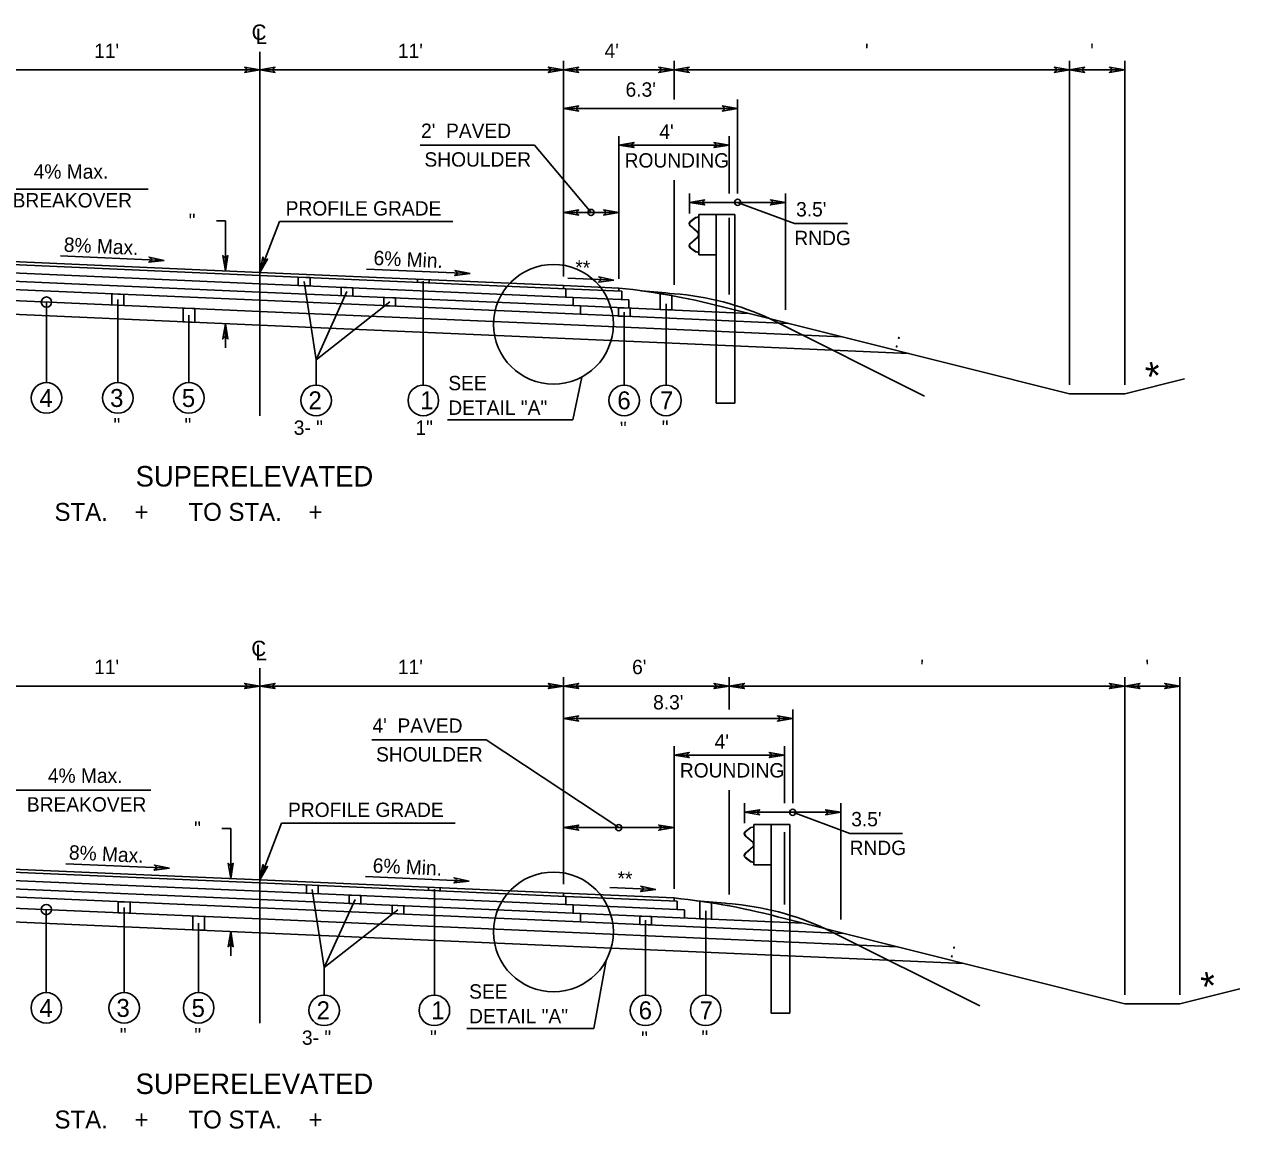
# Model space of a CAD drawing. Extents: x -592 to 1199, y -590 to 416.
# Drawn here: x 789.6 to 908.1, y -214.2 to -106.5 of the extents above; entities that cross this region are included whole.
import ezdxf

# ---------------------------------------------------------------- set-up
doc = ezdxf.new("R2010")
doc.units = 0
doc.layers.add('1', color=7, linetype='Continuous')
doc.layers.add('Des_ Drain_ Ftrs', color=7, linetype='Continuous')

msp = doc.modelspace()

# ---------------------------------------------------------------- linework, layer by layer
at = {"layer": '1'}
for p, q in [((812.53, -144.63), (812.53, -109.14)), ((842.16, -131.07), (842.16, -110.02)), ((852.94, -113.79), (852.94, -110.02)), ((891.52, -141.61), (891.52, -110.02)), ((896.91, -141.61), (896.91, -110.02)), ((812.53, -110.9), (782.89, -110.9)), ((812.53, -110.9), (842.16, -110.9)), ((842.16, -110.9), (852.94, -110.9)), ((852.94, -110.9), (891.52, -110.9)), ((891.52, -110.9), (896.91, -110.9)), ((859.14, -122.95), (859.14, -113.79)), ((842.16, -114.67), (859.14, -114.67)), ((847.55, -131.3), (847.55, -117.36)), ((858.33, -122.95), (858.33, -117.36)), ((839.32, -118.24), (828.18, -118.24)), ((844.85, -124.81), (839.32, -118.24)), ((847.55, -118.24), (858.33, -118.24)), ((852.94, -131.86), (852.94, -121.65)), ((801.62, -122.55), (787.67, -122.55)), ((854.44, -124.9), (854.44, -122.95)), ((863.83, -134.3), (863.83, -122.95)), ((854.44, -123.83), (863.83, -123.83)), ((859.14, -123.83), (864.69, -125.9)), ((809.17, -125.62), (808.29, -125.62)), ((809.17, -125.62), (809.17, -130.5)), ((842.16, -124.81), (847.55, -124.81)), ((855.04, -125.3), (854.52, -125.68)), ((855.05, -125.32), (854.54, -125.71)), ((855.36, -125.24), (855.04, -125.3)), ((855.36, -125.27), (855.05, -125.32)), ((855.36, -125.01), (855.36, -128.94)), ((855.36, -125.01), (857.04, -125.01)), ((857.04, -125.01), (857.04, -143.41)), ((858.87, -125.01), (857.04, -125.01)), ((858.33, -132.82), (858.33, -125.32)), ((858.87, -125.01), (858.87, -143.41)), ((812.53, -130.65), (814.44, -125.7)), ((831.35, -125.7), (814.44, -125.7)), ((854.51, -126.12), (855.24, -126.75)), ((854.53, -126.09), (855.26, -126.73)), ((864.69, -125.9), (869.85, -125.9)), ((855.24, -127.2), (854.51, -127.84)), ((855.26, -127.23), (854.53, -127.86)), ((855.33, -126.94), (855.33, -127.01)), ((855.36, -126.94), (855.36, -127.01)), ((793.09, -129.05), (803.21, -129.49)), ((854.52, -128.27), (855.04, -128.66)), ((854.54, -128.25), (855.05, -128.63)), ((855.04, -128.66), (855.36, -128.72)), ((855.05, -128.63), (855.36, -128.69)), ((855.36, -128.94), (857.04, -128.94)), ((812.53, -131.76), (781.62, -130.41)), ((812.53, -130.95), (782.54, -129.64)), ((812.53, -130.65), (782.88, -129.36)), ((822.93, -130.33), (833.04, -130.77)), ((812.53, -132.57), (780.7, -131.18)), ((842.17, -131.95), (812.53, -130.65)), ((842.4, -132.26), (812.53, -130.95)), ((816.86, -131.54), (818.02, -139.17)), ((828.48, -131.51), (828.48, -141.65)), ((847.07, -131.41), (842.58, -131.22)), ((812.53, -133.38), (780.7, -131.99)), ((843.1, -133.09), (812.53, -131.76)), ((843.81, -133.93), (812.53, -132.57)), ((821.03, -132.53), (818.02, -139.17)), ((847.55, -132.18), (842.17, -131.95)), ((842.17, -131.95), (842.17, -132.25)), ((847.84, -132.49), (842.4, -132.26)), ((842.4, -132.26), (842.4, -133.06)), ((847.55, -132.18), (847.55, -132.48)), ((847.84, -132.49), (847.84, -133.3)), ((812.53, -135.8), (758.02, -133.42)), ((812.53, -134.46), (780.7, -133.07)), ((791.71, -133.55), (791.71, -141.42)), ((798.68, -133.31), (798.68, -141.42)), ((843.81, -134.74), (812.53, -133.38)), ((825.21, -133.54), (818.02, -139.17)), ((848.54, -133.33), (843.1, -133.09)), ((843.1, -133.09), (843.1, -133.9)), ((843.81, -133.93), (843.81, -134.74)), ((860.16, -134.65), (843.81, -133.93)), ((848.54, -133.33), (848.54, -134.14)), ((852.16, -133.72), (852.16, -141.65)), ((854.44, -132.96), (854.44, -132.96)), ((805.61, -134.82), (805.61, -141.42)), ((842.17, -135.75), (812.53, -134.46)), ((864.08, -135.63), (843.81, -134.74)), ((848.08, -134.54), (848.08, -141.65)), ((858.33, -134.19), (891.52, -142.49)), ((809.17, -135.66), (809.17, -138.02)), ((875.84, -138.57), (812.53, -135.8)), ((869.31, -136.94), (842.17, -135.75)), ((862.33, -135.19), (877.38, -142.72)), ((818.02, -139.17), (818.02, -141.65)), ((843.96, -140.86), (843.07, -145.05)), ((902.74, -141.03), (896.91, -142.49)), ((858.87, -143.41), (857.04, -143.41)), ((891.52, -142.49), (896.91, -142.49)), ((830.84, -145.05), (843.07, -145.05)), ((812.53, -203.88), (812.53, -169.24)), ((842.16, -190.32), (842.16, -170.12)), ((858.33, -173.28), (858.33, -170.12)), ((896.91, -201.1), (896.91, -170.12)), ((902.3, -201.1), (902.3, -170.12)), ((812.53, -171), (782.89, -171)), ((812.53, -171), (842.16, -171)), ((842.16, -171), (858.33, -171)), ((858.33, -171), (896.91, -171)), ((896.91, -171), (902.3, -171)), ((842.16, -174.16), (864.52, -174.16)), ((864.52, -182.43), (864.52, -173.28)), ((834.6, -176.26), (823.46, -176.26)), ((847.55, -184.81), (834.6, -176.26)), ((852.94, -190.79), (852.94, -176.85)), ((852.94, -177.73), (863.71, -177.73)), ((863.71, -182.43), (863.71, -176.85)), ((801.91, -181.14), (788.43, -181.14)), ((858.33, -191.34), (858.33, -181.15)), ((859.83, -184.38), (859.83, -182.43)), ((869.21, -193.78), (869.21, -182.43)), ((859.83, -183.31), (869.21, -183.31)), ((864.52, -183.31), (870.08, -185.38)), ((809.69, -184.9), (808.81, -184.9)), ((809.69, -184.9), (809.69, -189.78)), ((812.53, -189.9), (814.66, -184.36)), ((831.58, -184.36), (814.66, -184.36)), ((842.16, -184.81), (852.94, -184.81)), ((860.42, -184.78), (859.91, -185.17)), ((860.44, -184.81), (859.93, -185.19)), ((860.74, -184.73), (860.42, -184.78)), ((860.74, -184.76), (860.44, -184.81)), ((860.74, -184.5), (860.74, -188.43)), ((860.74, -184.5), (862.42, -184.5)), ((862.42, -184.5), (862.42, -202.89)), ((864.25, -184.5), (862.42, -184.5)), ((864.25, -184.5), (864.25, -202.89)), ((859.89, -185.6), (860.62, -186.24)), ((859.91, -185.58), (860.64, -186.22)), ((863.71, -192.31), (863.71, -185.24)), ((870.08, -185.38), (875.23, -185.38)), ((860.62, -186.69), (859.89, -187.32)), ((860.64, -186.71), (859.91, -187.35)), ((860.71, -186.43), (860.71, -186.5)), ((860.74, -186.43), (860.74, -186.5)), ((793.6, -188.33), (803.71, -188.77)), ((859.91, -187.76), (860.42, -188.15)), ((859.93, -187.73), (860.44, -188.12)), ((860.42, -188.15), (860.74, -188.2)), ((860.44, -188.12), (860.74, -188.17)), ((860.74, -188.43), (862.42, -188.43)), ((812.53, -191.01), (781.62, -189.66)), ((812.53, -190.2), (782.54, -188.89)), ((812.53, -189.9), (782.88, -188.61)), ((822.85, -189.58), (832.96, -190.02)), ((812.53, -191.82), (780.7, -190.43)), ((842.17, -191.2), (812.53, -189.9)), ((842.4, -191.51), (812.53, -190.2)), ((817.65, -190.83), (818.81, -198.46)), ((829.56, -190.81), (829.56, -201.14)), ((851.17, -190.85), (846.67, -190.65)), ((812.53, -192.63), (780.72, -191.24)), ((843.1, -192.35), (812.53, -191.01)), ((843.81, -193.19), (812.53, -191.82)), ((821.83, -191.82), (818.81, -198.46)), ((852.94, -191.67), (842.17, -191.2)), ((842.17, -191.2), (842.17, -191.5)), ((853.26, -191.98), (842.4, -191.51)), ((842.4, -191.51), (842.4, -192.32)), ((852.94, -191.67), (852.94, -191.97)), ((853.26, -191.98), (853.26, -192.79)), ((812.53, -195.06), (753.04, -192.46)), ((812.53, -193.71), (780.7, -192.32)), ((791.7, -192.8), (791.7, -200.91)), ((799.29, -192.59), (799.29, -200.91)), ((843.81, -194), (812.53, -192.63)), ((826, -192.83), (818.81, -198.46)), ((853.96, -192.82), (843.1, -192.35)), ((843.1, -192.35), (843.1, -193.16)), ((843.81, -193.19), (843.81, -194)), ((865.55, -194.14), (843.81, -193.19)), ((853.96, -192.82), (853.96, -193.63)), ((856.03, -192.92), (856.03, -201.14)), ((859.83, -192.44), (859.83, -192.44)), ((806.56, -194.12), (806.56, -200.91)), ((843.77, -195.07), (812.53, -193.71)), ((869.47, -195.12), (843.81, -194)), ((850.16, -193.85), (850.16, -201.14)), ((863.71, -193.68), (896.91, -201.98)), ((809.69, -194.93), (809.69, -197.3)), ((881.23, -198.06), (812.53, -195.06)), ((874.7, -196.42), (843.77, -195.07)), ((867.71, -194.68), (882.76, -202.2)), ((846.31, -197.76), (845.13, -204.41)), ((818.81, -198.46), (818.81, -201.14)), ((908.13, -200.52), (902.3, -201.98)), ((896.91, -201.98), (902.3, -201.98)), ((864.25, -202.89), (862.42, -202.89)), ((832.73, -204.41), (845.13, -204.41))]:
    msp.add_line(p, q, dxfattribs=at)
for points in [[(816.28, -131.11), (817.43, -131.16), (817.43, -131.97), (816.28, -131.92)], [(827.91, -131.32), (829.05, -131.37), (829.05, -131.67), (827.91, -131.62)], [(798.1, -132.75), (799.25, -132.8), (799.25, -133.88), (798.1, -133.83)], [(820.46, -132.11), (821.6, -132.16), (821.6, -132.97), (820.46, -132.92)], [(851.59, -132.72), (852.73, -132.92), (852.73, -134.32), (851.59, -134.27)], [(824.63, -133.1), (825.78, -133.15), (825.78, -133.96), (824.63, -133.91)], [(805.04, -134.13), (806.18, -134.18), (806.18, -135.53), (805.04, -135.48)], [(847.51, -134.1), (848.65, -134.15), (848.65, -134.96), (847.51, -134.91)], [(817.08, -190.4), (818.22, -190.45), (818.22, -191.26), (817.08, -191.21)], [(828.99, -190.62), (830.13, -190.67), (830.13, -190.97), (828.99, -190.92)], [(798.72, -192.03), (799.87, -192.08), (799.87, -193.16), (798.72, -193.11)], [(821.25, -191.39), (822.4, -191.44), (822.4, -192.25), (821.25, -192.2)], [(855.46, -191.98), (856.61, -192.15), (856.61, -193.75), (855.46, -193.7)], [(825.43, -192.38), (826.58, -192.43), (826.58, -193.24), (825.43, -193.19)], [(805.99, -193.42), (807.13, -193.47), (807.13, -194.82), (805.99, -194.77)], [(849.59, -193.44), (850.73, -193.49), (850.73, -194.3), (849.59, -194.25)]]:
    msp.add_lwpolyline(points, close=True, dxfattribs=at)
for centre, radius in [((859.14, -123.83), 0.3), ((844.85, -124.81), 0.3), ((841.18, -135.72), 5.84), ((791.71, -133.55), 0.5), ((791.71, -142.9), 1.49), ((798.68, -142.9), 1.49), ((805.61, -142.9), 1.49), ((818.02, -143.14), 1.49), ((828.48, -143.14), 1.49), ((848.08, -143.14), 1.49), ((852.16, -143.14), 1.49), ((864.52, -183.31), 0.3), ((847.55, -184.81), 0.3), ((841.18, -194.98), 5.84), ((791.7, -192.8), 0.5), ((791.7, -202.39), 1.49), ((799.29, -202.39), 1.49), ((806.56, -202.39), 1.49), ((818.81, -202.63), 1.49), ((829.56, -202.63), 1.49), ((850.16, -202.63), 1.49), ((856.03, -202.63), 1.49)]:
    msp.add_circle(centre, radius, dxfattribs=at)
for centre, radius, start, end in [((854.69, -125.91), 0.278, 126.9799, 229.021), ((854.69, -125.91), 0.249, 126.9799, 229.021), ((855.08, -126.94), 0.249, 0, 49.0365), ((855.08, -126.94), 0.278, 0, 49.0365), ((854.69, -128.05), 0.278, 130.979, 233.0201), ((854.69, -128.05), 0.249, 130.979, 233.0201), ((855.08, -127.02), 0.249, 310.9635, 0), ((855.08, -127.02), 0.278, 310.9635, 0), ((840.66, -199.02), 67.19, 74.7593, 84.1179), ((842.12, -233.4), 101.24, 83.8633, 85.6775), ((850.82, -160.02), 27.37, 65.1374, 85.5513), ((860.07, -185.39), 0.278, 126.9799, 229.021), ((860.07, -185.39), 0.249, 126.9799, 229.021), ((860.07, -187.53), 0.278, 130.979, 233.0201), ((860.07, -187.53), 0.249, 130.979, 233.0201), ((860.46, -186.43), 0.249, 0, 49.0365), ((860.46, -186.5), 0.249, 310.9635, 0), ((860.46, -186.43), 0.278, 0, 49.0365), ((860.46, -186.5), 0.278, 310.9635, 0), ((846.05, -258.5), 67.19, 74.7602, 84.1188), ((847.5, -292.89), 101.24, 83.8633, 85.6775), ((856.2, -219.51), 27.37, 65.1374, 85.5513)]:
    msp.add_arc(centre, radius, start, end, dxfattribs=at)
at = {"layer": 'Des_ Drain_ Ftrs'}
for points in [[(812.53, -110.9), (811.04, -111.15), (811.33, -110.9), (811.04, -110.65)], [(812.53, -110.9), (814.01, -111.15), (813.72, -110.9), (814.01, -110.65)], [(842.16, -110.9), (840.67, -111.15), (840.97, -110.9), (840.67, -110.65)], [(842.16, -110.9), (843.65, -111.15), (843.35, -110.9), (843.65, -110.65)], [(852.94, -110.9), (851.45, -111.15), (851.74, -110.9), (851.45, -110.65)], [(852.94, -110.9), (854.43, -111.15), (854.13, -110.9), (854.43, -110.65)], [(891.52, -110.9), (890.04, -111.15), (890.33, -110.9), (890.04, -110.65)], [(891.52, -110.9), (893.01, -111.15), (892.72, -110.9), (893.01, -110.65)], [(896.91, -110.9), (895.42, -111.15), (895.72, -110.9), (895.42, -110.65)], [(842.16, -114.67), (843.65, -114.92), (843.36, -114.67), (843.65, -114.42)], [(859.14, -114.67), (857.65, -114.92), (857.94, -114.67), (857.65, -114.42)], [(847.55, -118.24), (849.04, -118.49), (848.74, -118.24), (849.04, -118)], [(858.33, -118.24), (856.84, -118.49), (857.13, -118.24), (856.84, -118)], [(854.44, -123.83), (855.93, -124.08), (855.64, -123.83), (855.93, -123.58)], [(863.83, -123.83), (862.34, -124.08), (862.63, -123.83), (862.34, -123.58)], [(842.16, -124.81), (843.65, -125.06), (843.35, -124.81), (843.65, -124.56)], [(847.55, -124.81), (846.06, -125.06), (846.36, -124.81), (846.06, -124.56)], [(803.21, -129.49), (801.71, -129.67), (802.01, -129.43), (801.73, -129.17)], [(809.17, -130.5), (809.41, -129.02), (809.17, -129.31), (808.92, -129.02)], [(812.53, -130.65), (813.29, -129.35), (812.95, -129.54), (812.83, -129.17)], [(833.04, -130.77), (831.54, -130.95), (831.85, -130.72), (831.56, -130.46)], [(847.07, -131.41), (845.58, -131.6), (845.88, -131.36), (845.6, -131.1)], [(809.17, -135.66), (809.41, -137.14), (809.17, -136.85), (808.92, -137.14)], [(812.53, -171), (811.04, -171.24), (811.33, -171), (811.04, -170.75)], [(812.53, -171), (814.01, -171.24), (813.72, -171), (814.01, -170.75)], [(842.16, -171), (840.67, -171.24), (840.97, -171), (840.67, -170.75)], [(842.16, -171), (843.65, -171.24), (843.35, -171), (843.65, -170.75)], [(858.33, -171), (856.84, -171.24), (857.13, -171), (856.84, -170.75)], [(858.33, -171), (859.81, -171.24), (859.52, -171), (859.81, -170.75)], [(896.91, -171), (895.42, -171.24), (895.72, -171), (895.42, -170.75)], [(896.91, -171), (898.4, -171.24), (898.11, -171), (898.4, -170.75)], [(902.3, -171), (900.81, -171.24), (901.11, -171), (900.81, -170.75)], [(842.16, -174.16), (843.65, -174.41), (843.35, -174.16), (843.65, -173.91)], [(864.52, -174.16), (863.03, -174.41), (863.33, -174.16), (863.03, -173.91)], [(852.94, -177.73), (854.43, -177.98), (854.13, -177.73), (854.43, -177.48)], [(863.71, -177.73), (862.23, -177.98), (862.52, -177.73), (862.23, -177.48)], [(859.83, -183.31), (861.31, -183.56), (861.02, -183.31), (861.31, -183.07)], [(869.21, -183.31), (867.72, -183.56), (868.02, -183.31), (867.72, -183.07)], [(842.16, -184.81), (843.65, -185.06), (843.35, -184.81), (843.65, -184.56)], [(852.94, -184.81), (851.45, -185.06), (851.74, -184.81), (851.45, -184.56)], [(803.71, -188.77), (802.22, -188.95), (802.52, -188.72), (802.24, -188.46)], [(809.69, -189.78), (809.94, -188.29), (809.69, -188.58), (809.45, -188.29)], [(812.53, -189.9), (813.29, -188.6), (812.95, -188.79), (812.83, -188.42)], [(832.96, -190.02), (831.46, -190.2), (831.77, -189.97), (831.49, -189.7)], [(851.17, -190.85), (849.67, -191.03), (849.98, -190.79), (849.69, -190.53)], [(809.69, -194.93), (809.94, -196.42), (809.69, -196.12), (809.45, -196.42)]]:
    msp.add_lwpolyline(points, close=True, dxfattribs=at)

# ---------------------------------------------------------------- texts
at = {"layer": '1'}
for s, height, p in [("11'", 1.4, (796.36, -109.75)), ("11'", 1.4, (826, -109.75)), ("4'", 1.4, (846.16, -109.75)), ("  '", 1.4, (870.53, -109.75)), (" '", 1.4, (893.02, -109.75)), ("6.3'", 1.4, (848.21, -113.52)), ("2'  PAVED", 1.4, (828.26, -117.54)), ("4'", 1.4, (851.51, -117.63)), ('SHOULDER', 1.4, (828.59, -120.34)), ('ROUNDING', 1.4, (848.12, -120.43)), ('4% Max.', 1.4, (790.46, -121.52)), ('BREAKOVER', 1.4, (788.41, -124.32)), ('PROFILE GRADE', 1.4, (815.05, -125.11)), ("3.5'", 1.4, (864.85, -125.2)), ('RNDG', 1.4, (864.68, -128)), ('SEE', 1.4, (830.92, -142.15)), ('4', 1.75, (791.03, -143.78)), ('3', 1.75, (797.92, -143.78)), ('5', 1.75, (804.92, -143.78)), ('2', 1.75, (817.27, -144.01)), ('1', 1.75, (828.18, -144.01)), ('6', 1.75, (847.41, -144.01)), ('7', 1.75, (851.57, -144.01)), ('DETAIL "A"', 1.4, (830.92, -144.55)), (' "', 1.4, (797.73, -146.26)), (' "', 1.4, (804.66, -146.26)), ('3- "', 1.4, (815.84, -146.5)), ('1"', 1.4, (827.71, -146.5)), (' "', 1.4, (847.14, -146.6)), (' "', 1.4, (851.22, -146.5)), ('SUPERELEVATED', 2, (800.41, -151.54)), ('STA.    +      TO STA.    +     ', 1.75, (792.5, -154.89)), ("11'", 1.4, (796.36, -169.84)), ("11'", 1.4, (826, -169.84)), ("6'", 1.4, (848.85, -169.84)), ("  '", 1.4, (875.92, -169.84)), (" '", 1.4, (898.41, -169.84)), ("8.3'", 1.4, (850.9, -173.28)), ("4'  PAVED", 1.4, (823.52, -175.56)), ("4'", 1.4, (856.9, -177.12)), ('SHOULDER', 1.4, (823.87, -178.36)), ('4% Max.', 1.4, (791.85, -180.44)), ('ROUNDING', 1.4, (853.51, -179.92)), ('BREAKOVER', 1.4, (789.8, -183.24)), ('PROFILE GRADE', 1.4, (815.28, -183.77)), ("3.5'", 1.4, (870.23, -184.68)), ('RNDG', 1.4, (870.07, -187.48)), ('SEE', 1.4, (832.95, -201.49)), ('4', 1.75, (791.02, -203.27)), ('3', 1.75, (798.54, -203.27)), ('5', 1.75, (805.87, -203.27)), ('2', 1.75, (818.07, -203.5)), ('1', 1.75, (829.26, -203.5)), ('DETAIL "A"', 1.4, (832.95, -203.89)), ('6', 1.75, (849.49, -203.5)), ('7', 1.75, (855.44, -203.5)), (' "', 1.4, (798.35, -205.75)), (' "', 1.4, (805.62, -205.75)), ('3- "', 1.4, (816.64, -205.99)), (' "', 1.4, (828.61, -205.99)), (' "', 1.4, (849.21, -206.08)), (' "', 1.4, (855.09, -205.99)), ('SUPERELEVATED', 2, (800.41, -210.79)), ('STA.    +      TO STA.    +     ', 1.75, (792.5, -214.15))]:
    msp.add_text(s, height=height, dxfattribs=at).set_placement(p)
for s, height, rotation, p in [('  "', 1.4, 0.1438, (804.55, -126.33)), ('8% Max.', 1.4, 357.376, (793.38, -128.63)), ('6% Min.', 1.4, 357.3732, (823.6, -129.93)), ('**', 1.4, 357.2164, (843.26, -130.85)), (' : ', 1.4, 345.7718, (873.88, -137.79)), ('*', 2.8, 12.8479, (899.37, -142.3)), ('  "', 1.4, 0.1438, (805.08, -185.6)), ('8% Max.', 1.4, 357.3769, (793.88, -187.91)), ('6% Min.', 1.4, 357.3725, (823.52, -189.18)), ('**', 1.4, 357.2506, (847.38, -190.44)), (' : ', 1.4, 345.7718, (879.26, -197.27)), ('*', 2.8, 12.8479, (904.76, -201.79))]:
    msp.add_text(s, height=height, rotation=rotation, dxfattribs=at).set_placement(p)
at = {"layer": 'Des_ Drain_ Ftrs'}
for s, p in [('C', (811.73, -107.98)), ('L', (812.12, -108.38)), ('C', (811.7, -168.08)), ('L', (812.1, -168.48))]:
    msp.add_text(s, height=1.5, dxfattribs=at).set_placement(p)

doc.saveas('drawing.dxf')
